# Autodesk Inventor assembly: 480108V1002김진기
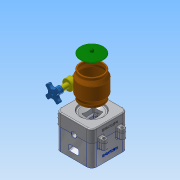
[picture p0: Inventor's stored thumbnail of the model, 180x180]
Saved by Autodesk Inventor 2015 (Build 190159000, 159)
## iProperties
Created: 2018-01
Part Number: 480108V1002김진기
Document SubType Name: Assembly
Designer: Administrator
Author: Administrator
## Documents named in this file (7)
- C:\Users\Administrator\Desktop\480108V1002김진기\480108V1002김진기.iam
- C:\Users\Administrator\Desktop\480108V1002김진기\480108V1002김진기.ipt
- C:\Users\Administrator\Desktop\480108V1002김진기\핸들.ipt
- C:\Users\Administrator\Desktop\480108V1002김진기\핸들축.ipt
- C:\Users\Administrator\Desktop\480108V1002김진기\본체커버.ipt
- C:\Users\Administrator\Desktop\480108V1002김진기\용기.ipt
- C:\Users\Administrator\Desktop\480108V1002김진기\용기캡.ipt
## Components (3 placed, 3 different names)
1. 480108V1002김진기:1
2. 핸들:1 — 각도:1
3. 핸들축:1 — 각도:1
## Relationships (1: Angle 1)
- 각도:1 [Angle]: 핸들:1 ↔ 핸들축:1
